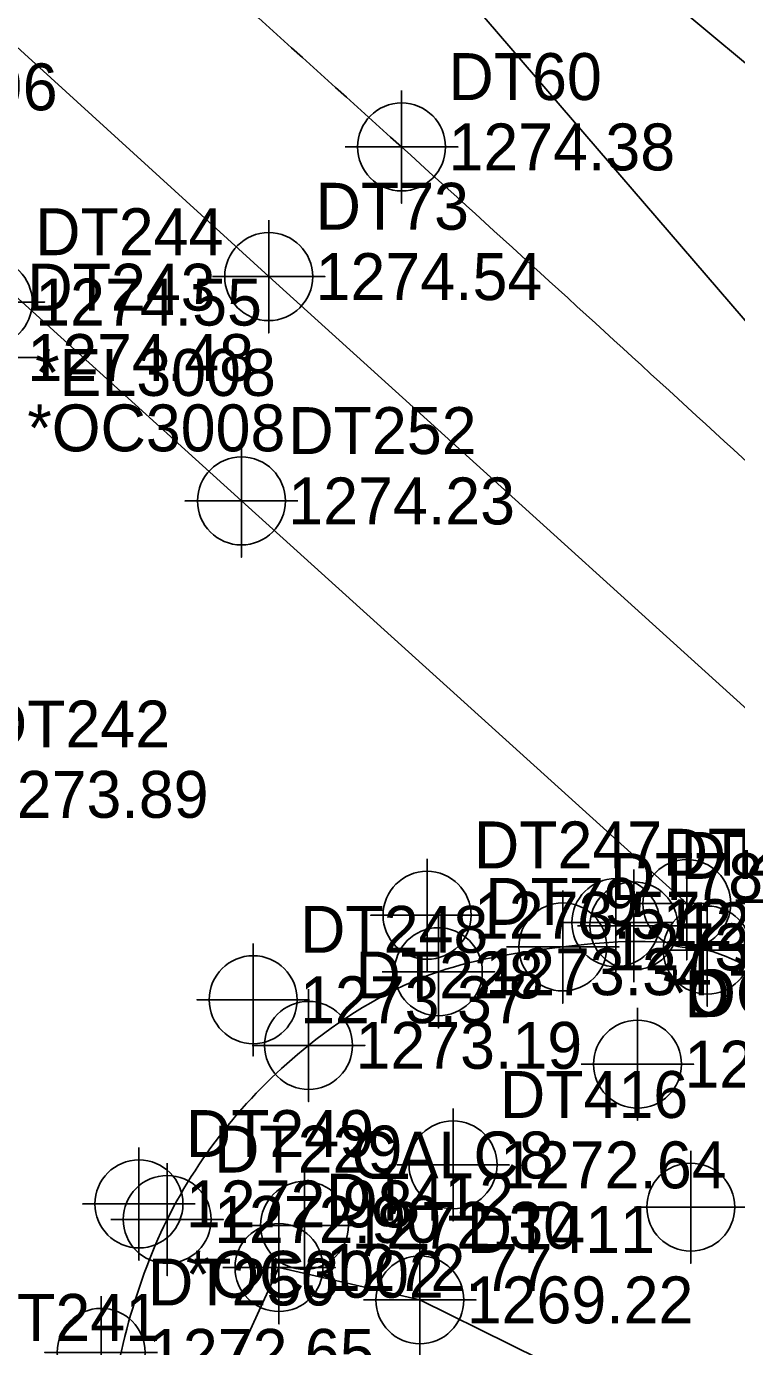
# Model space of a CAD drawing. Extents: x 1391270 to 1392151, y 960049 to 960667.
# Drawn here: x 1391507.1 to 1391545, y 960374.4 to 960444.8 of the extents above; entities that cross this region are included whole.
import ezdxf

# ---------------------------------------------------------------- set-up
doc = ezdxf.new("R2010")
doc.units = 0
for name, color, linetype in [('Cogo Default Point CELL', 7, 'Continuous'), ('COGO Default Point Elevation', 7, 'Continuous'), ('COGO Default Point Number', 7, 'Continuous'), ('Exist DTM Breakline', 7, 'Continuous'), ('Exist DTM Breakline Cogo Elevation', 7, 'Continuous'), ('Exist DTM Breakline Cogo Number', 7, 'Continuous'), ('Exist DTM Breakline Cogo Point CELL', 7, 'Continuous'), ('Exist DTM Crownline', 7, 'Continuous'), ('Exist DTM Crownline Cogo Comment', 7, 'Continuous'), ('Exist DTM Crownline Cogo Elevation', 7, 'Continuous'), ('Exist DTM Crownline Cogo Number', 7, 'Continuous'), ('Exist DTM Crownline Cogo Point CELL', 7, 'Continuous'), ('Exist DTM Regular Point CELL', 7, 'Continuous'), ('Exist DTM Regular Point Cogo Elevation', 7, 'Continuous'), ('Exist DTM Regular Point Cogo Number', 7, 'Continuous'), ('Exist Roads EOP', 7, 'Continuous'), ('Exist Roads EOP Cogo Elevation', 7, 'Continuous'), ('Exist Roads EOP Cogo Number', 7, 'Continuous'), ('Exist Roads EOP Cogo Point CELL', 7, 'Continuous'), ('Exist Roads EOT', 7, 'Continuous'), ('Exist Roads EOT Cogo Comment', 7, 'Continuous'), ('Exist Roads EOT Cogo Elevation', 7, 'Continuous'), ('Exist Roads EOT Cogo Number', 7, 'Continuous'), ('Exist Roads EOT Cogo Point CELL', 7, 'Continuous')]:
    doc.layers.add(name, color=color, linetype=linetype)

msp = doc.modelspace()

# ---------------------------------------------------------------- linework, layer by layer
at = {"layer": 'Cogo Default Point CELL'}
for points in [[(1391539.491, 960399.874), (1391539.491, 960396.874)], [(1391536.491, 960396.874), (1391539.491, 960396.874)], [(1391539.491, 960396.874), (1391542.491, 960396.874)], [(1391539.491, 960396.874), (1391539.491, 960393.874)], [(1391521.941, 960383.908), (1391521.941, 960380.908)], [(1391518.941, 960380.908), (1391521.941, 960380.908)], [(1391521.941, 960380.908), (1391524.941, 960380.908)], [(1391521.941, 960380.908), (1391521.941, 960377.908)]]:
    msp.add_lwpolyline(points, dxfattribs=at)
for centre in [(1391539.491, 960396.874), (1391521.941, 960380.908)]:
    msp.add_circle(centre, 2.344, dxfattribs=at)
at = {"layer": 'Exist DTM Breakline'}
for points in [[(1391572.148, 960404.532), (1391566.45, 960414.023), (1391560.493, 960420.45), (1391551.134, 960422.515), (1391527.127, 960450.418), (1391519.65, 960459.266), (1391497.478, 960479.87), (1391479.684, 960499.497), (1391463.962, 960505.846), (1391421.736, 960543.837), (1391384.984, 960575.223), (1391359.376, 960600.331), (1391347.861, 960610.635)], [(1391572.148, 960404.532), (1391576.459, 960415.363), (1391572.673, 960427.425), (1391557.483, 960432.832), (1391531.404, 960454.553)], [(1391593.208, 960393.183), (1391584.528, 960353.643), (1391570.827, 960358.056), (1391556.983, 960362.658), (1391528.086, 960376.935), (1391520.577, 960378.658), (1391515.927, 960368.512), (1391514.98, 960345.087), (1391519.249, 960311.75)]]:
    msp.add_lwpolyline(points, dxfattribs=at)
at = {"layer": 'Exist DTM Breakline Cogo Point CELL'}
for points in [[(1391520.577, 960381.658), (1391520.577, 960375.658), (1391520.577, 960378.658), (1391523.577, 960378.658), (1391517.577, 960378.658)], [(1391528.086, 960379.935), (1391528.086, 960373.935), (1391528.086, 960376.935), (1391531.086, 960376.935), (1391525.086, 960376.935)]]:
    msp.add_lwpolyline(points, dxfattribs=at)
for centre in [(1391520.577, 960378.658), (1391528.086, 960376.935)]:
    msp.add_circle(centre, 2.344, dxfattribs=at)
at = {"layer": 'Exist DTM Crownline'}
msp.add_lwpolyline([(1391336.775, 960598.787), (1391373.255, 960565.397), (1391410.328, 960531.742), (1391446.425, 960498.79), (1391483.147, 960465.095), (1391520.03, 960431.473), (1391553.996, 960400.745), (1391556.572, 960398.448)], dxfattribs=at)
at = {"layer": 'Exist DTM Crownline Cogo Point CELL'}
for points in [[(1391520.03, 960434.473), (1391520.03, 960428.473), (1391520.03, 960431.473), (1391523.03, 960431.473), (1391517.03, 960431.473)], [(1391505.082, 960433.114), (1391505.082, 960427.114), (1391505.082, 960430.114), (1391508.082, 960430.114), (1391502.082, 960430.114)], [(1391504.663, 960430.16), (1391504.663, 960424.16), (1391504.663, 960427.16), (1391507.663, 960427.16), (1391501.663, 960427.16)]]:
    msp.add_lwpolyline(points, dxfattribs=at)
for centre in [(1391520.03, 960431.473), (1391505.082, 960430.114)]:
    msp.add_circle(centre, 2.344, dxfattribs=at)
at = {"layer": 'Exist DTM Regular Point CELL'}
for points in [[(1391539.69, 960392.498), (1391539.69, 960386.498), (1391539.69, 960389.498), (1391542.69, 960389.498), (1391536.69, 960389.498)], [(1391529.857, 960387.131), (1391529.857, 960381.131), (1391529.857, 960384.131), (1391532.857, 960384.131), (1391526.857, 960384.131)], [(1391542.529, 960384.881), (1391542.529, 960378.881), (1391542.529, 960381.881), (1391545.529, 960381.881), (1391539.529, 960381.881)]]:
    msp.add_lwpolyline(points, dxfattribs=at)
for centre in [(1391539.69, 960389.498), (1391529.857, 960384.131), (1391542.529, 960381.881)]:
    msp.add_circle(centre, 2.344, dxfattribs=at)
at = {"layer": 'Exist Roads EOP'}
for points in [[(1391558.507, 960409.653), (1391527.113, 960438.384), (1391489.556, 960472.216), (1391453.007, 960506.097), (1391416.783, 960539.246), (1391379.565, 960572.597), (1391343.959, 960605.485)], [(1391553.715, 960387.967), (1391548.413, 960392.843), (1391543.408, 960395.581), (1391535.709, 960395.746), (1391529.074, 960394.424), (1391522.155, 960390.501), (1391514.618, 960381.223), (1391511.262, 960369.19), (1391511.324, 960340.675), (1391514.177, 960312.818)]]:
    msp.add_spline(points, degree=3, dxfattribs=at)
at = {"layer": 'Exist Roads EOP Cogo Point CELL'}
for points in [[(1391527.113, 960441.384), (1391527.113, 960435.384), (1391527.113, 960438.384), (1391530.113, 960438.384), (1391524.113, 960438.384)], [(1391535.709, 960398.746), (1391535.709, 960392.746), (1391535.709, 960395.746), (1391538.709, 960395.746), (1391532.709, 960395.746)], [(1391543.408, 960398.581), (1391543.408, 960392.581), (1391543.408, 960395.581), (1391546.408, 960395.581), (1391540.408, 960395.581)], [(1391529.074, 960397.424), (1391529.074, 960391.424), (1391529.074, 960394.424), (1391532.074, 960394.424), (1391526.074, 960394.424)], [(1391522.155, 960393.501), (1391522.155, 960387.501), (1391522.155, 960390.501), (1391525.155, 960390.501), (1391519.155, 960390.501)], [(1391514.618, 960384.223), (1391514.618, 960378.223), (1391514.618, 960381.223), (1391517.618, 960381.223), (1391511.618, 960381.223)]]:
    msp.add_lwpolyline(points, dxfattribs=at)
for centre in [(1391527.113, 960438.384), (1391535.709, 960395.746), (1391543.408, 960395.581), (1391529.074, 960394.424), (1391522.155, 960390.501), (1391514.618, 960381.223)]:
    msp.add_circle(centre, 2.344, dxfattribs=at)
at = {"layer": 'Exist Roads EOT'}
msp.add_lwpolyline([(1391542.319, 960398.059), (1391518.576, 960419.517), (1391494.192, 960441.585), (1391465.739, 960467.932), (1391455.599, 960477.451)], dxfattribs=at)
at = {"layer": 'Exist Roads EOT Cogo Point CELL'}
for points in [[(1391518.576, 960422.517), (1391518.576, 960416.517), (1391518.576, 960419.517), (1391515.576, 960419.517), (1391521.576, 960419.517)], [(1391542.319, 960401.059), (1391542.319, 960395.059), (1391542.319, 960398.059), (1391539.319, 960398.059), (1391545.319, 960398.059)], [(1391528.47, 960400.434), (1391528.47, 960394.434), (1391528.47, 960397.434), (1391525.47, 960397.434), (1391531.47, 960397.434)], [(1391538.533, 960400.042), (1391538.533, 960394.042), (1391538.533, 960397.042), (1391535.533, 960397.042), (1391541.533, 960397.042)], [(1391519.201, 960395.933), (1391519.201, 960389.933), (1391519.201, 960392.933), (1391516.201, 960392.933), (1391522.201, 960392.933)], [(1391513.113, 960385.05), (1391513.113, 960379.05), (1391513.113, 960382.05), (1391510.113, 960382.05), (1391516.113, 960382.05)], [(1391511.094, 960377.137), (1391511.094, 960371.137), (1391511.094, 960374.137), (1391508.094, 960374.137), (1391514.094, 960374.137)]]:
    msp.add_lwpolyline(points, dxfattribs=at)
for centre in [(1391518.576, 960419.517), (1391528.47, 960397.434), (1391542.319, 960398.059), (1391538.533, 960397.042), (1391519.201, 960392.933), (1391513.113, 960382.05), (1391511.094, 960374.137)]:
    msp.add_circle(centre, 2.344, dxfattribs=at)

# ---------------------------------------------------------------- texts
at = {"layer": 'COGO Default Point Elevation'}
for s, p in [('1273.69', (1391541.991, 960395.624)), ('1272.30', (1391524.441, 960379.658))]:
    msp.add_text(s, height=2.5, dxfattribs=at).set_placement(p)
at = {"layer": 'COGO Default Point Number'}
for s, p in [('DT245', (1391541.991, 960399.374)), ('CALC8', (1391524.441, 960383.408))]:
    msp.add_text(s, height=2.5, dxfattribs=at).set_placement(p)
at = {"layer": 'Exist DTM Breakline Cogo Elevation'}
for s, p in [('1272.77', (1391523.077, 960377.408)), ('1269.22', (1391530.586, 960375.685))]:
    msp.add_text(s, height=2.5, dxfattribs=at).set_placement(p)
at = {"layer": 'Exist DTM Breakline Cogo Number'}
for s, p in [('DT412', (1391523.077, 960381.158)), ('DT411', (1391530.586, 960379.435))]:
    msp.add_text(s, height=2.5, dxfattribs=at).set_placement(p)
at = {"layer": 'Exist DTM Crownline Cogo Comment'}
for s, p in [('*EL3008', (1391507.582, 960425.114)), ('*OC3008', (1391507.163, 960422.16))]:
    msp.add_text(s, height=2.5, dxfattribs=at).set_placement(p)
at = {"layer": 'Exist DTM Crownline Cogo Elevation'}
for s, p in [('1274.54', (1391522.53, 960430.223)), ('1274.55', (1391507.582, 960428.864)), ('1274.48', (1391507.163, 960425.91)), ('1273.89', (1391504.738, 960402.627))]:
    msp.add_text(s, height=2.5, dxfattribs=at).set_placement(p)
at = {"layer": 'Exist DTM Crownline Cogo Number'}
for s, p in [('DT73', (1391522.53, 960433.973)), ('DT244', (1391507.582, 960432.614)), ('DT243', (1391507.163, 960429.66)), ('DT242', (1391504.738, 960406.377)), ('DT241', (1391504.201, 960374.752))]:
    msp.add_text(s, height=2.5, dxfattribs=at).set_placement(p)
at = {"layer": 'Exist DTM Regular Point Cogo Elevation'}
for s, p in [('1272.93', (1391542.19, 960388.248)), ('1272.64', (1391532.357, 960382.881))]:
    msp.add_text(s, height=2.5, dxfattribs=at).set_placement(p)
at = {"layer": 'Exist DTM Regular Point Cogo Number'}
for s, p in [('DT417', (1391542.19, 960391.998)), ('DT416', (1391532.357, 960386.631))]:
    msp.add_text(s, height=2.5, dxfattribs=at).set_placement(p)
at = {"layer": 'Exist Roads EOP Cogo Elevation'}
for s, p in [('1274.38', (1391529.613, 960437.134)), ('1273.48', (1391538.209, 960394.496)), ('1273.34', (1391531.574, 960393.174)), ('1273.19', (1391524.655, 960389.251)), ('1272.90', (1391517.118, 960379.973))]:
    msp.add_text(s, height=2.5, dxfattribs=at).set_placement(p)
at = {"layer": 'Exist Roads EOP Cogo Number'}
for s, p in [('DT60', (1391529.613, 960440.884)), ('DT78', (1391538.209, 960398.246)), ('DT79', (1391531.574, 960396.924)), ('DT228', (1391524.655, 960393.001)), ('DT229', (1391517.118, 960383.723))]:
    msp.add_text(s, height=2.5, dxfattribs=at).set_placement(p)
at = {"layer": 'Exist Roads EOT Cogo Comment'}
for s, p in [('*BL3002', (1391544.819, 960393.059)), ('*OC3002', (1391541.033, 960392.042)), ('*OC3002', (1391515.613, 960377.05))]:
    msp.add_text(s, height=2.5, dxfattribs=at).set_placement(p)
at = {"layer": 'Exist Roads EOT Cogo Elevation'}
for s, p in [('1274.96', (1391496.692, 960440.335)), ('1274.23', (1391521.076, 960418.267)), ('1273.57', (1391530.97, 960396.184)), ('1273.69', (1391541.033, 960395.792)), ('1273.37', (1391521.701, 960391.683)), ('1272.98', (1391515.613, 960380.8)), ('1272.65', (1391513.594, 960372.887))]:
    msp.add_text(s, height=2.5, dxfattribs=at).set_placement(p)
at = {"layer": 'Exist Roads EOT Cogo Number'}
for s, p in [('DT252', (1391521.076, 960422.017)), ('DT247', (1391530.97, 960399.934)), ('DT246', (1391541.033, 960399.542)), ('DT248', (1391521.701, 960395.433)), ('DT249', (1391515.613, 960384.55)), ('DT250', (1391513.594, 960376.637))]:
    msp.add_text(s, height=2.5, dxfattribs=at).set_placement(p)

doc.saveas('drawing.dxf')
